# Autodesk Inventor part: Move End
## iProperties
Created: 2005-12
Part Number: Move End
Document SubType Name: Modeling
Designer: home user
Manufacturer: Standard
Standards Organization: Custom
Author: home user
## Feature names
1. Extrusion1
2. Extrusion2
3. Chamfer1
4. Hole1
5. Hole2
6. Hole3
7. Hole4
8. Hole5
9. Hole6
10. Chamfer2
11. Chamfer3
12. Hole7
13. Hole8
14. Hole9
